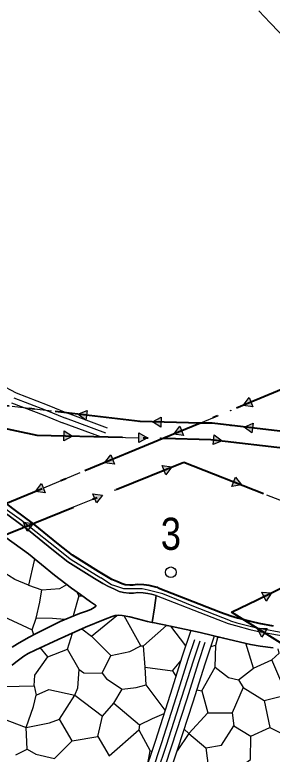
# Model space of a CAD drawing. Extents: x -64005 to -55000, y -89025 to -80000.
# Drawn here: x -59524 to -59043, y -84506 to -83126 of the extents above; entities that cross this region are included whole.
import ezdxf
from ezdxf.enums import TextEntityAlignment as Align

# ---------------------------------------------------------------- set-up
doc = ezdxf.new("R2010")
doc.units = 0
doc.header["$LTSCALE"] = 32
for name, pattern in [('DASH_DOUBLE_DOT', [9.2, 5, -1.2, 0.3, -1.2, 0.3, -1.2]), ('DOT_DASHED', [7.7, 5, -1.2, 0.3, -1.2]), ('LONG_DASHED', [7.5, 6, -1.5])]:
    doc.linetypes.add(name, pattern=pattern)
for name, color, linetype, lineweight in [('18', 7, 'Continuous', 25), ('19', 7, 'Continuous', 25), ('24', 7, 'Continuous', 25), ('3', 7, 'Continuous', 25), ('39', 7, 'LONG_DASHED', 25), ('52', 7, 'Continuous', 25), ('53', 7, 'DASH_DOUBLE_DOT', 25), ('6', 7, 'Continuous', 25), ('8', 7, 'Continuous', 25)]:
    doc.layers.add(name, color=color, linetype=linetype, lineweight=lineweight)
doc.layers.add('38', color=7, linetype='Continuous')

msp = doc.modelspace()

# ---------------------------------------------------------------- hatches: boundary and pattern name
at = {"layer": '18'}
for points in [[(-59079.16, -83857.58), (-59097.5, -83855.15), (-59086.23, -83840.49)], [(-59391.31, -83882.71), (-59406.13, -83871.65), (-59389.14, -83864.34)], [(-59251.15, -83895.52), (-59266.95, -83885.9), (-59250.71, -83877.03)], [(-59208.55, -83911.06), (-59226.88, -83908.63), (-59215.61, -83893.96)], [(-59080.81, -83906.59), (-59095.64, -83895.53), (-59078.65, -83888.21)], [(-59432.09, -83902.81), (-59416.29, -83912.43), (-59432.52, -83921.3)], [(-59292.13, -83906.07), (-59276.33, -83915.69), (-59292.56, -83924.56)], [(-59151.34, -83909.87), (-59136.51, -83920.93), (-59153.5, -83928.24)], [(-59337.93, -83964.53), (-59356.27, -83962.1), (-59345, -83947.43)], [(-59248.79, -83967.36), (-59230.47, -83969.89), (-59241.83, -83984.5)], [(-59111.81, -83988.97), (-59100.29, -84003.44), (-59118.58, -84006.19)], [(-59467.31, -84018.01), (-59485.65, -84015.58), (-59474.38, -84000.91)], [(-59378.48, -84020.09), (-59360.16, -84022.62), (-59371.52, -84037.23)], [(-59508.17, -84072.82), (-59489.85, -84075.36), (-59501.21, -84089.96)], [(-59062.44, -84203.58), (-59043.98, -84204.8), (-59054.27, -84220.17)], [(-59062.42, -84287.41), (-59071.14, -84271.09), (-59052.65, -84271.7)]]:
    msp.add_hatch(color=256, dxfattribs=at).paths.add_polyline_path(points)

# ---------------------------------------------------------------- linework, layer by layer
for p, q in [((-59014.32, -83820.78), (-59082.69, -83849.03)), ((-59455.79, -83865.78), (-59529.25, -83857.09)), ((-59316.75, -83882.21), (-59390.22, -83873.53)), ((-59006.25, -83906.05), (-59079.73, -83897.4)), ((-59366.31, -83913.59), (-59292.35, -83915.31)), ((-59273.09, -83927.72), (-59341.46, -83955.98)), ((-59086.85, -83926.77), (-59013.38, -83935.42)), ((-59313.84, -84003.79), (-59245.31, -83975.93)), ((-59184.04, -83970.5), (-59115.2, -83997.58)), ((-59402.48, -83981.2), (-59470.85, -84009.46)), ((-59443.53, -84056.52), (-59375, -84028.66)), ((-59053.76, -84021.74), (-58984.91, -84048.82)), ((-58994.71, -84318.62), (-59057.54, -84279.55))]:
    msp.add_line(p, q, dxfattribs=at)
at = {"layer": '18', "linetype": 'DOT_DASHED', "lineweight": 40}
for points in [[(-55000.81, -81341.27), (-57492.65, -83191.85), (-58506.34, -83610.82), (-59176.97, -83888), (-59245.7, -83916.4), (-60498.5, -84434.2), (-61697.45, -84700.56), (-63379.7, -85074.29), (-63500.32, -85101.08), (-63736.4, -85153.53), (-64000, -85168.65)], [(-62511.18, -83419.68), (-62511.65, -83442.16), (-62269.37, -83547.46), (-62236.29, -83546.11), (-61998.23, -83536.37), (-61478.42, -83639.63), (-61155.09, -83677.73), (-60626.09, -83739.21), (-60379.64, -83770.49), (-59836.37, -83832.74), (-59632.07, -83878.3), (-59482.83, -83910.88), (-59245.7, -83916.4), (-59157.46, -83918.46), (-58274.27, -84022.41)], [(-59176.97, -83888), (-59290.14, -83885.36), (-59657.06, -83841.98), (-59831.38, -83803.11), (-60376.04, -83740.71), (-60622.47, -83709.43), (-61151.6, -83647.93), (-61473.73, -83609.97), (-61992.38, -83506.94), (-61993.6, -83506.74), (-62420.8, -83437.27), (-62481.72, -83419.68)], [(-55000.53, -84382.79), (-55516.56, -84320.09), (-55729.93, -84231.35), (-55898.21, -84162.02), (-56153.65, -84175.49), (-56582.99, -84192.51), (-56626.76, -84187.31), (-57504.59, -84083.05), (-58001.88, -84024.51), (-58160.87, -84004.69), (-58191.9, -84001.28), (-58270.88, -83992.6), (-59155.35, -83888.5), (-59176.97, -83888)], [(-64000, -85400.95), (-63756.78, -85343.55), (-63583.22, -85302.6), (-63160.94, -85202.94), (-62774.07, -85111.63), (-62063.05, -84888.71), (-61746.39, -84828.12), (-61731.7, -84825.31), (-61594.06, -84786.87), (-61360.14, -84721.55), (-60481.8, -84478.68), (-59562.86, -84105.04), (-59208.4, -83960.92), (-58840.52, -84105.61)], [(-57909.63, -84889.76), (-57997.85, -84809.51), (-58160.08, -84671.97), (-58262.78, -84580.02), (-58369.05, -84484.65), (-58431.62, -84437.88), (-58487.55, -84415.84), (-58559.03, -84397.83), (-58865.43, -84345.37), (-58984.38, -84325.05), (-59119.11, -84241.26), (-59071.31, -84218.26), (-58962.91, -84164.86), (-58840.52, -84105.61), (-58831.32, -84101.16), (-58719.42, -84046.06), (-58601.22, -84047.86), (-58515.22, -84046.86), (-58297.39, -84050.36), (-58215.09, -84059.35), (-58137.14, -84068.11)]]:
    msp.add_lwpolyline(points, dxfattribs=at)
at = {"layer": '18'}
for points in [[(-59079.16, -83857.58), (-59097.5, -83855.15), (-59086.23, -83840.49)], [(-59391.31, -83882.71), (-59406.13, -83871.65), (-59389.14, -83864.34)], [(-59251.15, -83895.52), (-59266.95, -83885.9), (-59250.71, -83877.03)], [(-59208.55, -83911.06), (-59226.88, -83908.63), (-59215.61, -83893.96)], [(-59080.81, -83906.59), (-59095.64, -83895.53), (-59078.65, -83888.21)], [(-59432.09, -83902.81), (-59416.29, -83912.43), (-59432.52, -83921.3)], [(-59292.13, -83906.07), (-59276.33, -83915.69), (-59292.56, -83924.56)], [(-59151.34, -83909.87), (-59136.51, -83920.93), (-59153.5, -83928.24)], [(-59337.93, -83964.53), (-59356.27, -83962.1), (-59345, -83947.43)], [(-59248.79, -83967.36), (-59230.47, -83969.89), (-59241.83, -83984.5)], [(-59111.81, -83988.97), (-59100.29, -84003.44), (-59118.58, -84006.19)], [(-59467.31, -84018.01), (-59485.65, -84015.58), (-59474.38, -84000.91)], [(-59378.48, -84020.09), (-59360.16, -84022.62), (-59371.52, -84037.23)], [(-59508.17, -84072.82), (-59489.85, -84075.36), (-59501.21, -84089.96)], [(-59062.44, -84203.58), (-59043.98, -84204.8), (-59054.27, -84220.17)], [(-59062.42, -84287.41), (-59071.14, -84271.09), (-59052.65, -84271.7)]]:
    msp.add_lwpolyline(points, close=True, dxfattribs=at)
for points in [[(-59143.71, -83874.25), (-59176.97, -83888), (-59212.08, -83902.51)], [(-59145.29, -83889.68), (-59155.35, -83888.5), (-59176.97, -83888), (-59250.93, -83886.27)], [(-59505.74, -83905.88), (-59482.83, -83910.88), (-59432.31, -83912.06)], [(-59226.34, -83916.85), (-59157.46, -83918.46), (-59152.42, -83919.05)], [(-59573.22, -84109.25), (-59562.86, -84105.04), (-59504.69, -84081.39)], [(-59113.6, -84244.69), (-59119.11, -84241.26), (-59071.31, -84218.26), (-59058.35, -84211.88)]]:
    msp.add_lwpolyline(points, dxfattribs=at)
for centre in [(-59430.96, -83868.71), (-59120.6, -83864.7), (-59291.93, -83885.15), (-59120.46, -83892.61), (-59391.3, -83913.01), (-59251.34, -83916.27), (-59249.99, -83918.17), (-59111.68, -83923.85), (-59207.31, -83961.35), (-59379.37, -83971.65), (-59337, -84013.21), (-59077.02, -84012.59), (-59508.76, -84025.13), (-59466.69, -84065.94), (-59092.37, -84257.89)]:
    msp.add_circle(centre, 0.5, dxfattribs=at)
at = {"layer": '19'}
for p, q in [((-59404.48, -84210.7), (-59398.53, -84210.34)), ((-59204.59, -84303.62), (-59232.54, -84267.4)), ((-59488.66, -84283.12), (-59492.1, -84273.71)), ((-59144.9, -84288.25), (-59141.73, -84287.49)), ((-59229.46, -84350.37), (-59222.93, -84360.4)), ((-59243.18, -84423.68), (-59278.78, -84376.81)), ((-59199.1, -84467.42), (-59220.51, -84499.91)), ((-59275.74, -84523.29), (-59270.95, -84500.03))]:
    msp.add_line(p, q, dxfattribs=at)
for points in [[(-59557.43, -84090.17), (-59498.82, -84132.43), (-59450.35, -84171.86), (-59418.04, -84196.34), (-59401.61, -84208.21), (-59382.45, -84221.45), (-59373.16, -84227.65), (-59372.51, -84228.48), (-59372.48, -84229.1), (-59373.23, -84230.44), (-59375.78, -84232.55), (-59382.17, -84236.1), (-59390.38, -84239.31), (-59401.32, -84242.58), (-59406.68, -84244.55), (-59439.49, -84258.71), (-59455.71, -84266.26), (-59484.35, -84280.79), (-59498.45, -84288.42), (-59519.39, -84300.36), (-59528.99, -84306.26)], [(-59487.53, -84141.61), (-59488.25, -84144.67), (-59498.46, -84190.86), (-59524.2, -84179.75), (-59535.75, -84172.65), (-59553.5, -84161.1)], [(-59546.7, -84248.6), (-59492.1, -84273.71), (-59484.61, -84252.12), (-59477.57, -84222.16), (-59473.6, -84199.3)], [(-59498.46, -84190.86), (-59473.6, -84199.3), (-59439.86, -84196.63), (-59427.21, -84189.39)], [(-59408.22, -84203.44), (-59404.48, -84210.7), (-59415.02, -84248.15)], [(-59529.27, -84340.11), (-59522.62, -84334.63), (-59507.13, -84323.42), (-59499.03, -84318.38), (-59486.39, -84311.7), (-59443.08, -84291.88), (-59392.13, -84269.23), (-59355.06, -84253.94), (-59342.04, -84248.85), (-59336.8, -84247.4), (-59334.14, -84247.01), (-59330.15, -84246.86), (-59323.25, -84247.33), (-59309.48, -84249.69), (-59295.08, -84253.32), (-59276.05, -84258.28), (-59266.46, -84260.45), (-59233.35, -84267.23), (-59195.13, -84275.22)], [(-59430.45, -84254.81), (-59453.79, -84252.56), (-59484.61, -84252.12)], [(-59399.19, -84272.37), (-59380.93, -84286.04), (-59333.35, -84246.98)], [(-59380.93, -84286.04), (-59344.82, -84322.18), (-59309.16, -84314.25), (-59288.46, -84303.67), (-59319.99, -84247.89)], [(-59288.46, -84303.67), (-59283.62, -84304.11), (-59240.48, -84265.77)], [(-59462.61, -84324.38), (-59425.61, -84310.28), (-59416.6, -84280.11)], [(-59195.13, -84275.22), (-59211.13, -84323.24), (-59233.79, -84394.58), (-59262.05, -84482.19), (-59284.37, -84549.17), (-59289.6, -84568.13)], [(-59245.76, -84578.39), (-59241.3, -84562.27), (-59219.28, -84496.22), (-59190.95, -84408.3), (-59168.34, -84337.16), (-59151.06, -84285.31)], [(-59157.63, -84305.04), (-59148.44, -84302.79), (-59144.9, -84288.25), (-59146.1, -84286.47)], [(-59151.06, -84285.31), (-59133.99, -84289.3), (-59083.33, -84301.18), (-59065.41, -84304.5), (-59041.28, -84307.76)], [(-59544.06, -84379.45), (-59488.14, -84378.58), (-59486.82, -84358.31), (-59462.61, -84324.38), (-59476.63, -84307.23)], [(-59488.14, -84378.58), (-59484.19, -84395.76), (-59460.4, -84385.61), (-59411.97, -84395.76), (-59406.25, -84382.09), (-59404.04, -84348.16), (-59425.61, -84310.28)], [(-59361.13, -84354.78), (-59352.74, -84365.35), (-59323.25, -84384.74), (-59297.28, -84381.66), (-59278.78, -84376.81), (-59280.53, -84343.76), (-59283.62, -84304.11)], [(-59183.95, -84386.27), (-59174.85, -84387.82), (-59149.31, -84343.76), (-59148.44, -84302.79)], [(-59149.31, -84343.76), (-59124.65, -84363.15), (-59106.16, -84367.56), (-59077.98, -84345.52), (-59092.04, -84299.14)], [(-59077.98, -84345.52), (-59043.62, -84329.66), (-59029.98, -84317.33), (-59031.83, -84309.26)], [(-59404.04, -84348.16), (-59395.02, -84354.34), (-59361.13, -84354.78), (-59344.82, -84322.18)], [(-59280.53, -84343.76), (-59229.46, -84350.37), (-59213.8, -84331.65)], [(-59106.16, -84367.56), (-59097.35, -84381.66), (-59057.73, -84405.89), (-59015.45, -84395.31), (-59043.62, -84329.66)], [(-59411.97, -84395.76), (-59360.35, -84434.82), (-59339.2, -84411.03), (-59323.25, -84384.74)], [(-59174.85, -84387.82), (-59163.43, -84429.09), (-59117.64, -84428.65)], [(-59097.35, -84381.66), (-59117.64, -84428.65), (-59115, -84453.32), (-59082.85, -84472.27), (-59047.62, -84456.4)], [(-59547.48, -84439.66), (-59503.01, -84456.4), (-59489.35, -84417.2), (-59484.19, -84395.76)], [(-59503.01, -84456.4), (-59459.42, -84447.6), (-59440.48, -84440.99), (-59411.97, -84395.76)], [(-59057.73, -84405.89), (-59047.62, -84456.4), (-59006.68, -84476.68)], [(-59339.2, -84411.03), (-59291.21, -84451.56), (-59266.56, -84439.22), (-59245.22, -84430)], [(-59417.14, -84481.08), (-59369.15, -84473.16), (-59360.35, -84434.82)], [(-59207.41, -84459.38), (-59199.1, -84467.42), (-59163.43, -84429.09)], [(-59501.25, -84496.94), (-59484.96, -84506.19), (-59450.18, -84514.13), (-59417.14, -84481.08), (-59440.48, -84440.99)], [(-59522.14, -84507.58), (-59501.25, -84496.94), (-59503.01, -84456.4)], [(-59369.15, -84473.16), (-59347.58, -84509.28), (-59292.53, -84460.38)], [(-59291.21, -84451.56), (-59292.53, -84460.38), (-59270.95, -84500.03), (-59268.25, -84500.8)], [(-59199.1, -84467.42), (-59166.97, -84494.3), (-59137.9, -84489.46), (-59115, -84453.32)], [(-59166.97, -84494.3), (-59162.12, -84533.07), (-59143.18, -84538.8), (-59118.97, -84541.44), (-59083.73, -84515.88), (-59082.85, -84472.27)]]:
    msp.add_lwpolyline(points, dxfattribs=at)
at = {"layer": '24'}
msp.add_lwpolyline([(-58999.37, -83190), (-59047.05, -83140.92), (-59067.89, -83118.41)], dxfattribs=at)
at = {"layer": '3', "lineweight": 40}
for points in [[(-59256.04, -84195.53), (-59256.89, -84195.2), (-59260.6, -84194.11), (-59265.36, -84192.95), (-59272.95, -84191.38), (-59282.72, -84189.9), (-59295.38, -84189.52), (-59303.16, -84190.68), (-59309.29, -84190.58), (-59317.85, -84189.75), (-59323.7, -84188.03), (-59333.37, -84183.64), (-59342.6, -84179.81), (-59352.34, -84174.56), (-59367.49, -84165.17), (-59416.52, -84134.62), (-59442.47, -84114.05), (-59489.43, -84076.26), (-59525.59, -84049.5), (-59544.03, -84035.08), (-59565.16, -84023.81), (-59573.86, -84017.79)], [(-59256.04, -84195.53), (-59139.51, -84240.83), (-59120.37, -84247.66), (-59107.57, -84251.63), (-59081.29, -84258.53), (-59068.1, -84261.51), (-59041.24, -84266.82)]]:
    msp.add_lwpolyline(points, dxfattribs=at)
at = {"layer": '3'}
for points in [[(-59256.04, -84195.53), (-59256.89, -84195.2), (-59260.6, -84194.11), (-59265.36, -84192.95), (-59272.95, -84191.38), (-59282.72, -84189.9), (-59295.38, -84189.52), (-59303.16, -84190.68), (-59309.29, -84190.58), (-59317.85, -84189.75), (-59323.7, -84188.03), (-59333.37, -84183.64), (-59342.6, -84179.81), (-59352.34, -84174.56), (-59367.49, -84165.17), (-59416.52, -84134.62), (-59442.47, -84114.05), (-59489.43, -84076.26), (-59525.59, -84049.5), (-59544.03, -84035.08), (-59565.16, -84023.81), (-59573.86, -84017.79)], [(-59259.82, -84209.98), (-59264.5, -84208.59), (-59268.64, -84207.59), (-59275.6, -84206.15), (-59284.07, -84204.86), (-59294.49, -84204.55), (-59302.17, -84205.7), (-59310.13, -84205.57), (-59320.72, -84204.55), (-59328.95, -84202.12), (-59339.35, -84197.4), (-59349.05, -84193.37), (-59359.86, -84187.54), (-59375.4, -84177.91), (-59425.17, -84146.9), (-59451.83, -84125.77), (-59498.6, -84088.14), (-59534.68, -84061.44), (-59554.86, -84047.78), (-59572.9, -84036.68), (-59582.7, -84029.96)], [(-59582.7, -84029.96), (-59572.9, -84036.68), (-59554.86, -84047.78), (-59534.68, -84061.44), (-59498.6, -84088.14), (-59451.83, -84125.77), (-59425.17, -84146.9), (-59375.4, -84177.91), (-59359.86, -84187.54), (-59349.05, -84193.37), (-59339.35, -84197.4), (-59328.95, -84202.12), (-59320.72, -84204.55), (-59310.13, -84205.57), (-59302.17, -84205.7), (-59294.49, -84204.55), (-59284.07, -84204.86), (-59275.6, -84206.15), (-59268.64, -84207.59), (-59264.5, -84208.59), (-59259.82, -84209.98)], [(-59041.24, -84266.82), (-59068.1, -84261.51), (-59081.29, -84258.53), (-59107.57, -84251.63), (-59120.37, -84247.66), (-59139.51, -84240.83), (-59256.04, -84195.53)], [(-59259.82, -84209.98), (-59144.75, -84254.89), (-59125.11, -84261.9), (-59111.69, -84266.05), (-59084.85, -84273.11), (-59071.2, -84276.19), (-59043.96, -84281.58), (-58962.22, -84295.56)], [(-59259.82, -84209.98), (-59144.75, -84254.89), (-59125.11, -84261.9), (-59111.69, -84266.05), (-59084.85, -84273.11), (-59071.2, -84276.19), (-59043.96, -84281.58), (-58962.22, -84295.56)]]:
    msp.add_lwpolyline(points, dxfattribs=at)
at = {"layer": '39'}
msp.add_line((-59354.2, -83906.79), (-59429.48, -83878.85), dxfattribs=at)
for points in [[(-59526.02, -83840.92), (-59467.43, -83863.17), (-59429.48, -83878.85)], [(-59273.78, -84595.37), (-59262.84, -84555.72), (-59240.66, -84489.2), (-59212.37, -84401.44), (-59189.73, -84330.2), (-59177.83, -84294.47)]]:
    msp.add_lwpolyline(points, dxfattribs=at)
at = {"layer": '52'}
msp.add_circle((-59232.44, -84166.58), 10, dxfattribs=at)
at = {"layer": '53'}
for points in [[(-59550.95, -84041.54), (-59511.89, -84069.16), (-59458.34, -84111.61), (-59421.49, -84140.92), (-59418.6, -84142.99), (-59363.52, -84176.84)], [(-59120.68, -84257.35), (-59192.77, -84229.06), (-59221.06, -84217.27), (-59247.44, -84207.06), (-59254.69, -84205.2), (-59275.02, -84200.03), (-59285.97, -84197.59), (-59302.89, -84197.73), (-59320.41, -84197.39), (-59336.98, -84192.02), (-59343.21, -84189.82), (-59363.52, -84176.84)], [(-59120.68, -84257.35), (-59109.05, -84261.03), (-59076.39, -84269.05), (-58952.29, -84291.94)]]:
    msp.add_lwpolyline(points, dxfattribs=at)
at = {"layer": '6', "lineweight": 35}
for points in [[(-59557.43, -84090.17), (-59498.82, -84132.43), (-59450.35, -84171.86), (-59418.04, -84196.34), (-59401.61, -84208.21), (-59382.45, -84221.45), (-59373.16, -84227.65), (-59372.51, -84228.48), (-59372.48, -84229.1), (-59373.23, -84230.44), (-59375.78, -84232.55), (-59382.17, -84236.1), (-59390.38, -84239.31), (-59401.32, -84242.58), (-59406.68, -84244.55), (-59439.49, -84258.71), (-59455.71, -84266.26), (-59484.35, -84280.79), (-59498.45, -84288.42), (-59519.39, -84300.36), (-59528.99, -84306.26)], [(-59259.82, -84209.98), (-59263.2, -84233.21), (-59267.41, -84260.23)], [(-59267.41, -84260.23), (-59276.05, -84258.27), (-59295.08, -84253.32), (-59309.48, -84249.69), (-59323.25, -84247.33), (-59330.15, -84246.86), (-59334.14, -84247.01), (-59336.8, -84247.4), (-59342.04, -84248.85), (-59355.06, -84253.94), (-59392.13, -84269.23), (-59443.08, -84291.88), (-59486.39, -84311.7), (-59499.03, -84318.38), (-59507.13, -84323.42), (-59522.62, -84334.63), (-59529.27, -84340.11)], [(-59267.41, -84260.23), (-59266.46, -84260.45), (-59233.35, -84267.23), (-59177.59, -84279.12), (-59133.99, -84289.3), (-59083.33, -84301.18), (-59065.41, -84304.49), (-59041.28, -84307.76)]]:
    msp.add_lwpolyline(points, dxfattribs=at)
at = {"layer": '8'}
msp.add_line((-59350.94, -83897.34), (-59426, -83869.48), dxfattribs=at)
at = {"layer": '8', "linetype": 'LONG_DASHED'}
msp.add_line((-59362.11, -83914.47), (-59435.17, -83887.32), dxfattribs=at)
at = {"layer": '8'}
for points in [[(-59552.84, -83815.23), (-59521.87, -83831.8), (-59463.74, -83853.87), (-59426, -83869.48)], [(-59261.47, -84588.36), (-59253.27, -84558.62), (-59231.16, -84492.32), (-59202.85, -84404.49), (-59180.22, -84333.29), (-59168.05, -84296.75)]]:
    msp.add_lwpolyline(points, dxfattribs=at)
at = {"layer": '8', "linetype": 'LONG_DASHED'}
for points in [[(-59530.17, -83850.04), (-59471.12, -83872.47), (-59435.17, -83887.32)], [(-59280.81, -84583.26), (-59272.41, -84552.81), (-59250.16, -84486.08), (-59221.89, -84398.39), (-59199.24, -84327.11), (-59187.62, -84292.22)]]:
    msp.add_lwpolyline(points, dxfattribs=at)

# ---------------------------------------------------------------- texts
at = {"layer": '38', "width": 0.85}
msp.add_text('3', height=60, rotation=0.007, dxfattribs=at).set_placement((-59232.42, -84124.71), align=Align.CENTER)

doc.saveas('drawing.dxf')
